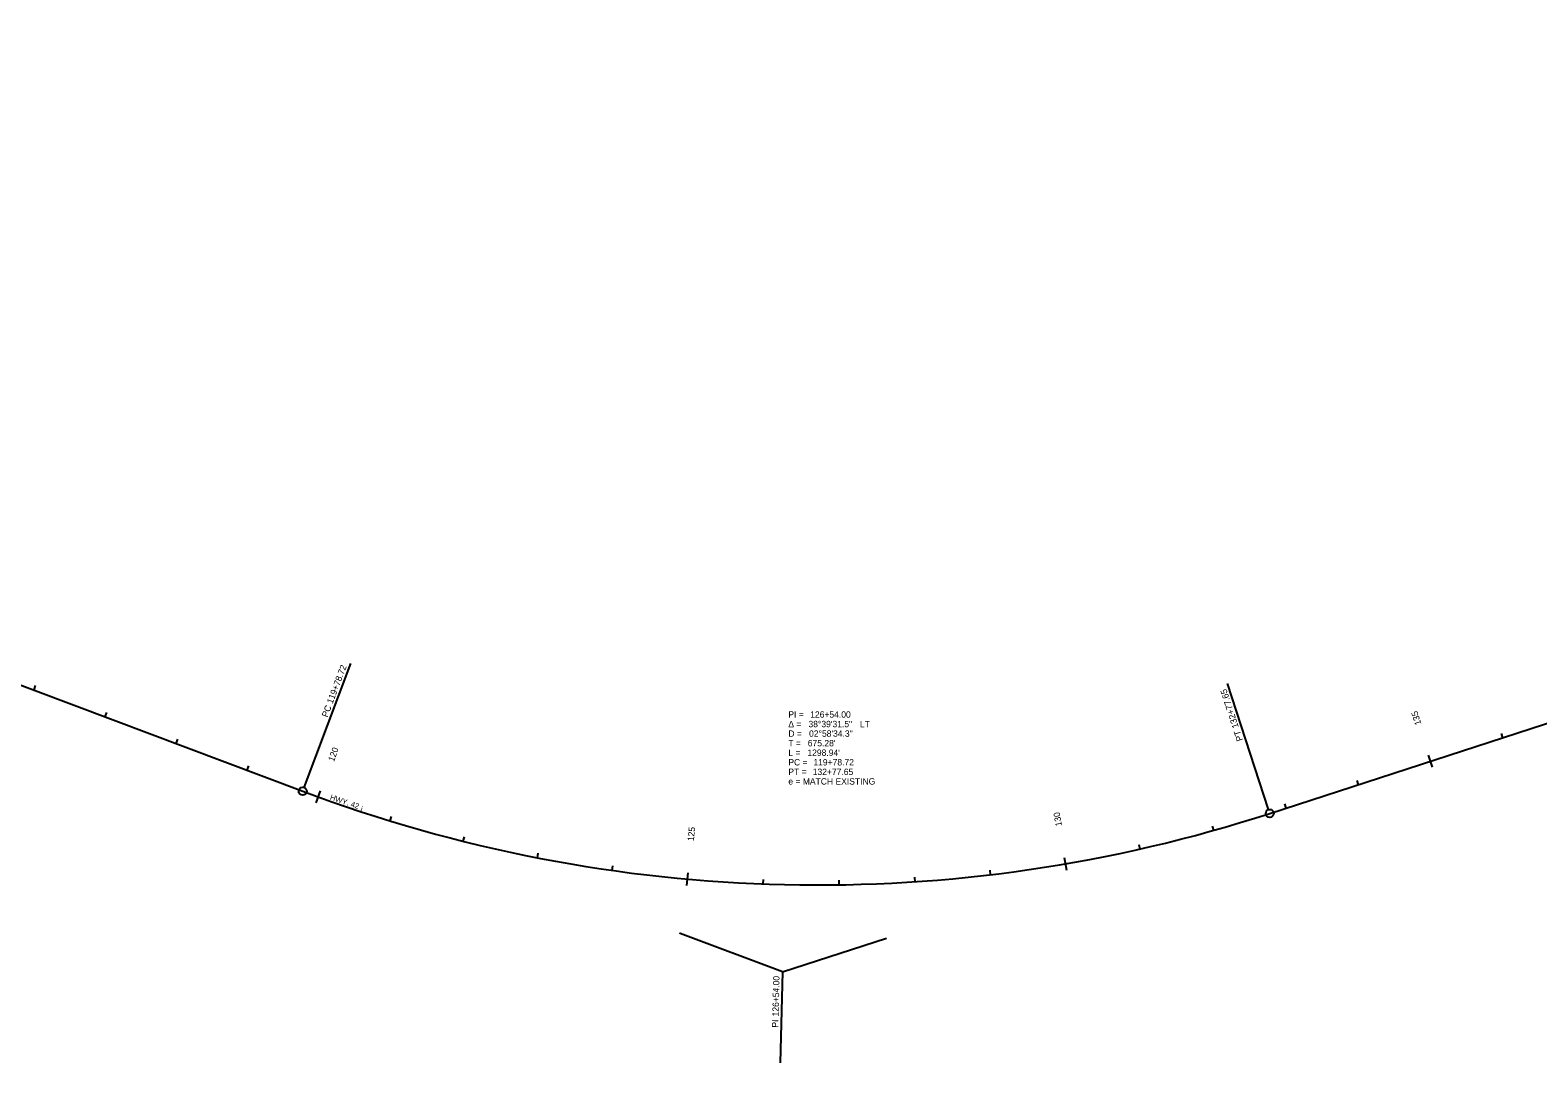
# Model space of a CAD drawing. Extents: x 1707563 to 1725852, y 372271 to 382824.
# Drawn here: x 1714747 to 1716733, y 376096 to 377457 of the extents above; entities that cross this region are included whole.
import ezdxf

# ---------------------------------------------------------------- set-up
doc = ezdxf.new("R2010")
doc.units = 0
for name, color, linetype in [('Default', 7, 'Continuous'), ('DSN_ROW_Line', 7, 'Continuous'), ('DSN_ROW_Point-Annotation', 7, 'Continuous'), ('DSN_ROW_Temp-Esmnt', 7, 'Continuous'), ('S_PHOTO_NOTES', 7, 'Continuous'), ('S_TRAILS', 7, 'Continuous')]:
    doc.layers.add(name, color=color, linetype=linetype)

msp = doc.modelspace()

# ---------------------------------------------------------------- linework, layer by layer
at = {"layer": 'Default'}
for p, q in [((1716380, 376424.9), (1719554.6, 377457.3)), ((1714315.4, 376752), (1715105.9, 376454.1))]:
    msp.add_line(p, q, dxfattribs=at)
msp.add_arc((1715784.6, 378255.7), 1925.1, 249.3561, 288.0149, dxfattribs=at)
at = {"layer": 'DSN_ROW_Line'}
msp.add_circle((1715603.1, 376266.8), 0.05, dxfattribs=at)
at = {"layer": 'DSN_ROW_Point-Annotation'}
for p, q in [((1715107.8, 376459.1), (1715169.4, 376622.6)), ((1715169.4, 376622.6), (1715169.4, 376622.6)), ((1714753.6, 376593.3), (1714751.5, 376587.7)), ((1716378.3, 376430), (1716324.3, 376596.1)), ((1716324.3, 376596.1), (1716324.3, 376596.1)), ((1714847.2, 376558), (1714845.1, 376552.4)), ((1714940.8, 376522.8), (1714938.6, 376517.1)), ((1716684.7, 376530.3), (1716686.5, 376524.6)), ((1716588.8, 376501.6), (1716594, 376485.7)), ((1715034.3, 376487.5), (1715032.2, 376481.9)), ((1716494.5, 376468.4), (1716496.3, 376462.7)), ((1715105.9, 376454.1), (1715105.9, 376454.1)), ((1715128.7, 376454.6), (1715123, 376438.8)), ((1716399.4, 376437.5), (1716401.2, 376431.8)), ((1715222.4, 376420.7), (1715220.7, 376415)), ((1716380, 376424.9), (1716380, 376424.9)), ((1716304.1, 376408.2), (1716305.7, 376402.4)), ((1715318.4, 376394), (1715317, 376388.2)), ((1716207.4, 376383.7), (1716208.8, 376377.8)), ((1715415.7, 376372.3), (1715414.6, 376366.4)), ((1716109.3, 376366.6), (1716112.1, 376350.1)), ((1715514, 376355.7), (1715513.2, 376349.8)), ((1715613.2, 376346.6), (1715611.7, 376329.9)), ((1715911.8, 376340.7), (1715912.2, 376334.7)), ((1716011, 376349.9), (1716011.7, 376344)), ((1715712.5, 376337.9), (1715712.3, 376331.9)), ((1715812.2, 376336.7), (1715812.3, 376330.7)), ((1715737.8, 376216.1), (1715603.1, 376266.8)), ((1715737.8, 376216.1), (1715874.8, 376260.6)), ((1715737.8, 376216.1), (1715735.1, 376096.1)), ((1715735.1, 376096.1), (1715735.1, 376096.1))]:
    msp.add_line(p, q, dxfattribs=at)
for centre in [(1715105.9, 376454.1), (1716380, 376424.9)]:
    msp.add_circle(centre, 5.34, dxfattribs=at)
at = {"layer": 'DSN_ROW_Temp-Esmnt'}
for p, q in [((1716380, 376424.9), (1719554.6, 377457.3)), ((1714315.4, 376752), (1715105.9, 376454.1))]:
    msp.add_line(p, q, dxfattribs=at)
msp.add_arc((1715784.6, 378255.7), 1925.1, 249.3561, 288.0149, dxfattribs=at)

# ---------------------------------------------------------------- texts
at = {"layer": 'Default'}
msp.add_text('HWY. 42 ¡', height=7.2, rotation=341.2344, dxfattribs=at).set_placement((1715141.2, 376443.3))
at = {"layer": 'DSN_ROW_Point-Annotation'}
for s, rotation, p in [('119+78.72', 69.3561, (1715145.2, 376568.7)), ('132+77.65', 108.0149, (1716339.2, 376538.8)), ('PC', 69.3561, (1715138.5, 376550.9)), ('135', 108.0149, (1716579.9, 376542.8)), ('PT', 108.0149, (1716344.8, 376521.6)), ('120', 69.9896, (1715147, 376492.5)), ('130', 99.7515, (1716106.3, 376408.6)), ('125', 84.8705, (1715621.2, 376388))]:
    msp.add_text(s, height=8.4, rotation=rotation, dxfattribs=at).set_placement(p)
at = {"layer": 'S_PHOTO_NOTES'}
for s, p in [('PI = ', (1715745.7, 376551.1)), ('126+54.00', (1715774.5, 376551.1)), ('Δ = ', (1715745.7, 376538.5)), ('38°39\'31.5"', (1715772.2, 376538.5)), (' LT', (1715836.9, 376538.5)), ('T = ', (1715745.7, 376513.3)), ('D = ', (1715745.7, 376525.9)), ("675.28'", (1715771.3, 376513.3)), ('02°58\'34.3"', (1715773, 376525.9)), ('L = ', (1715745.7, 376500.7)), ("1298.94'", (1715770.8, 376500.7)), ('PC = ', (1715745.7, 376488.1)), ('PT = ', (1715745.7, 376475.5)), ('132+77.65', (1715777.8, 376475.5)), ('119+78.72', (1715778.7, 376488.1)), ('e = MATCH EXISTING', (1715745.7, 376462.9))]:
    msp.add_text(s, height=8.4, dxfattribs=at).set_placement(p)
at = {"layer": 'S_TRAILS'}
for s, p in [('126+54.00', (1715732.9, 376157.2)), ('PI ', (1715732.5, 376142.4))]:
    msp.add_text(s, height=8.4, rotation=88.6855, dxfattribs=at).set_placement(p)

doc.saveas('drawing.dxf')
